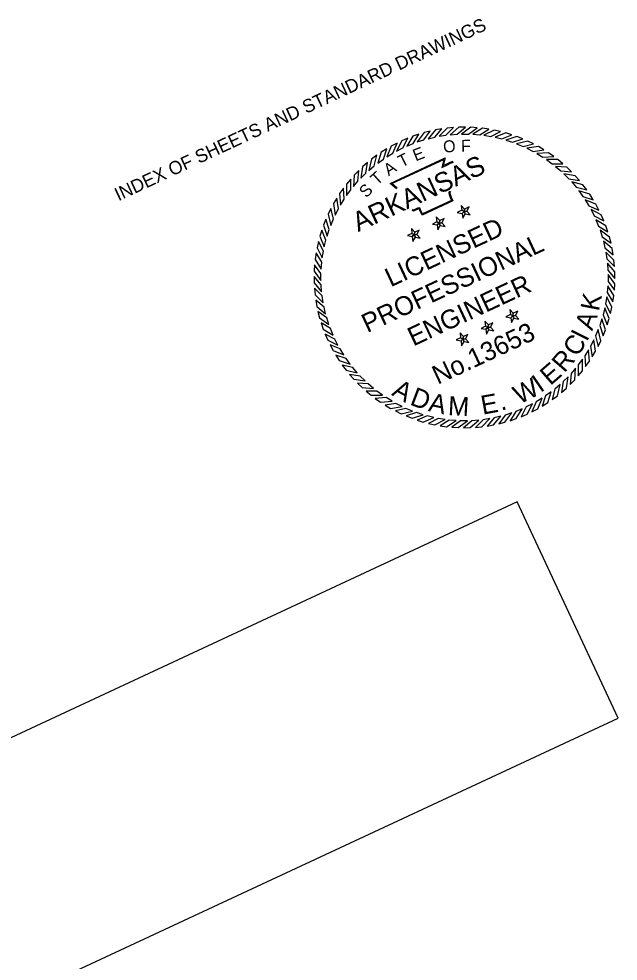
# Model space of a CAD drawing. Extents: x 756658 to 763719, y 1656413 to 1661090.
# Drawn here: x 758763 to 759240, y 1658253 to 1659003 of the extents above; entities that cross this region are included whole.
import ezdxf

# ---------------------------------------------------------------- set-up
doc = ezdxf.new("R2010")
doc.units = 0
doc.layers.add('1', color=7, linetype='Continuous')
doc.layers.add('G-ANNO-STMP-AEW', color=7, linetype='Continuous')

msp = doc.modelspace()

# ---------------------------------------------------------------- linework, layer by layer
at = {"layer": '1'}
msp.add_lwpolyline([(758071.66, 1657901.4), (759239.96, 1658446.19), (759159.72, 1658618.28), (757991.41, 1658073.49)], close=True, dxfattribs=at)
at = {"layer": 'G-ANNO-STMP-AEW'}
for points in [[(759099.83, 1658915.18), (759094.76, 1658914.3), (759088.81, 1658907.32), (759094.22, 1658908.6)], [(759109.17, 1658916.22), (759104.05, 1658915.74), (759097.56, 1658909.26), (759103.05, 1658910.11)], [(759118.56, 1658916.53), (759113.41, 1658916.45), (759106.44, 1658910.5), (759111.98, 1658910.92)], [(759127.94, 1658916.1), (759122.8, 1658916.43), (759115.39, 1658911.04), (759120.94, 1658911.02)], [(759137.26, 1658914.94), (759132.17, 1658915.67), (759124.35, 1658910.88), (759129.89, 1658910.42)], [(759072.72, 1658907.71), (759068, 1658905.67), (759063.83, 1658897.5), (759068.79, 1658900.01)], [(759081.55, 1658910.91), (759076.68, 1658909.25), (759071.89, 1658901.43), (759077.03, 1658903.54)], [(759090.61, 1658913.4), (759085.62, 1658912.13), (759080.23, 1658904.71), (759085.53, 1658906.41)], [(759146.46, 1658913.05), (759141.44, 1658914.17), (759133.27, 1658910.01), (759138.76, 1658909.12)], [(759155.49, 1658910.44), (759150.57, 1658911.96), (759142.1, 1658908.45), (759147.5, 1658907.13)], [(759164.28, 1658907.14), (759159.49, 1658909.03), (759150.77, 1658906.2), (759156.05, 1658904.46)], [(759064.16, 1658903.84), (759059.62, 1658901.43), (759056.11, 1658892.96), (759060.85, 1658895.85)], [(759172.78, 1658903.15), (759168.16, 1658905.42), (759159.25, 1658903.27), (759164.38, 1658901.13)], [(759180.95, 1658898.51), (759176.52, 1658901.13), (759167.47, 1658899.69), (759172.41, 1658897.16)], [(759048.1, 1658894.13), (759043.98, 1658891.04), (759041.84, 1658882.13), (759046.08, 1658885.72)], [(759055.94, 1658899.3), (759051.59, 1658896.54), (759048.76, 1658887.82), (759053.27, 1658891.08)], [(759188.73, 1658893.24), (759184.52, 1658896.2), (759175.38, 1658895.48), (759180.11, 1658892.56)], [(759040.68, 1658888.36), (759036.82, 1658884.96), (759035.39, 1658875.9), (759039.33, 1658879.82)], [(759196.07, 1658887.38), (759192.1, 1658890.66), (759182.93, 1658890.66), (759187.42, 1658887.38)], [(759202.92, 1658880.96), (759199.23, 1658884.54), (759190.09, 1658885.26), (759194.3, 1658881.64)], [(759033.74, 1658882.03), (759030.16, 1658878.34), (759029.44, 1658869.19), (759033.07, 1658873.41)], [(759209.26, 1658874.02), (759205.86, 1658877.88), (759196.8, 1658879.32), (759200.72, 1658875.37)], [(759027.32, 1658875.17), (759024.04, 1658871.21), (759024.04, 1658862.04), (759027.32, 1658866.53)], [(759215.02, 1658866.61), (759211.94, 1658870.72), (759203.02, 1658872.86), (759206.62, 1658868.63)], [(759021.46, 1658867.83), (759018.5, 1658863.62), (759019.22, 1658854.48), (759022.14, 1658859.21)], [(759220.19, 1658858.76), (759217.44, 1658863.11), (759208.72, 1658865.94), (759211.97, 1658861.44)], [(759016.19, 1658860.05), (759013.57, 1658855.63), (759015.01, 1658846.57), (759017.55, 1658851.52)], [(759224.73, 1658850.54), (759222.33, 1658855.09), (759213.85, 1658858.6), (759216.74, 1658853.85)], [(759011.55, 1658851.89), (759009.29, 1658847.27), (759011.43, 1658838.35), (759013.57, 1658843.48)], [(759117.49, 1658849.32), (759115.67, 1658850.34), (759112.06, 1658848.66), (759115.96, 1658847.9)], [(759117.49, 1658849.32), (759117.89, 1658851.37), (759115.18, 1658854.28), (759115.67, 1658850.34)], [(759117.49, 1658849.32), (759115.96, 1658847.9), (759116.45, 1658843.95), (759118.38, 1658847.43)], [(759117.49, 1658849.32), (759119.57, 1658849.58), (759121.49, 1658853.05), (759117.89, 1658851.37)], [(759117.49, 1658849.32), (759118.38, 1658847.43), (759122.28, 1658846.67), (759119.57, 1658849.58)], [(759228.61, 1658841.98), (759226.57, 1658846.71), (759218.4, 1658850.87), (759220.91, 1658845.91)], [(759007.57, 1658843.38), (759005.67, 1658838.6), (759008.5, 1658829.88), (759010.24, 1658835.16)], [(759097.67, 1658840.08), (759095.84, 1658841.09), (759092.24, 1658839.41), (759096.14, 1658838.65)], [(759097.67, 1658840.08), (759098.07, 1658842.13), (759095.36, 1658845.03), (759095.84, 1658841.09)], [(759097.67, 1658840.08), (759096.14, 1658838.65), (759096.62, 1658834.71), (759098.55, 1658838.18)], [(759097.67, 1658840.08), (759099.74, 1658840.33), (759101.67, 1658843.81), (759098.07, 1658842.13)], [(759097.67, 1658840.08), (759098.55, 1658838.18), (759102.45, 1658837.43), (759099.74, 1658840.33)], [(759231.81, 1658833.15), (759230.14, 1658838.02), (759222.32, 1658842.81), (759224.43, 1658837.67)], [(759004.26, 1658834.59), (759002.74, 1658829.67), (759006.25, 1658821.2), (759007.57, 1658826.6)], [(759077.84, 1658830.83), (759078.24, 1658832.88), (759075.53, 1658835.79), (759076.01, 1658831.85)], [(759077.84, 1658830.83), (759079.91, 1658831.09), (759081.84, 1658834.56), (759078.24, 1658832.88)], [(759234.3, 1658824.1), (759233.02, 1658829.08), (759225.6, 1658834.47), (759227.3, 1658829.18)], [(759001.65, 1658825.57), (759000.53, 1658820.55), (759004.69, 1658812.38), (759005.58, 1658817.86)], [(759077.84, 1658830.83), (759076.01, 1658831.85), (759072.41, 1658830.17), (759076.31, 1658829.41)], [(759077.84, 1658830.83), (759076.31, 1658829.41), (759076.8, 1658825.46), (759078.72, 1658828.94)], [(759077.84, 1658830.83), (759078.72, 1658828.94), (759082.62, 1658828.18), (759079.91, 1658831.09)], [(759236.07, 1658814.87), (759235.19, 1658819.94), (759228.22, 1658825.89), (759229.5, 1658820.49)], [(758999.76, 1658816.36), (758999.03, 1658811.27), (759003.83, 1658803.45), (759004.28, 1658808.99)], [(759237.12, 1658805.54), (759236.64, 1658810.66), (759230.15, 1658817.14), (759231, 1658811.65)], [(758998.6, 1658807.04), (758998.27, 1658801.91), (759003.66, 1658794.49), (759003.68, 1658800.05)], [(759237.43, 1658796.15), (759237.35, 1658801.29), (759231.39, 1658808.26), (759231.81, 1658802.72)], [(758998.17, 1658797.66), (758998.25, 1658792.52), (759004.2, 1658785.54), (759003.79, 1658791.09)], [(759237, 1658786.76), (759237.32, 1658791.9), (759231.93, 1658799.32), (759231.92, 1658793.76)], [(758998.48, 1658788.27), (758998.96, 1658783.15), (759005.45, 1658776.67), (759004.59, 1658782.16)], [(759235.84, 1658777.44), (759236.56, 1658782.54), (759231.77, 1658790.35), (759231.32, 1658784.81)], [(759233.94, 1658768.24), (759235.07, 1658773.26), (759230.91, 1658781.43), (759230.02, 1658775.95)], [(758999.53, 1658778.94), (759000.41, 1658773.87), (759007.38, 1658767.91), (759006.1, 1658773.32)], [(759231.34, 1658759.22), (759232.85, 1658764.13), (759229.34, 1658772.61), (759228.03, 1658767.21)], [(759001.3, 1658769.71), (759002.58, 1658764.73), (759009.99, 1658759.34), (759008.29, 1658764.63)], [(759156.21, 1658766.3), (759154.38, 1658767.32), (759150.78, 1658765.64), (759154.68, 1658764.88)], [(759156.21, 1658766.3), (759156.6, 1658768.35), (759153.89, 1658771.26), (759154.38, 1658767.32)], [(759156.21, 1658766.3), (759154.68, 1658764.88), (759155.16, 1658760.93), (759157.09, 1658764.41)], [(759156.21, 1658766.3), (759158.28, 1658766.56), (759160.2, 1658770.03), (759156.6, 1658768.35)], [(759156.21, 1658766.3), (759157.09, 1658764.41), (759160.99, 1658763.65), (759158.28, 1658766.56)], [(759003.79, 1658760.66), (759005.46, 1658755.79), (759013.27, 1658751), (759011.16, 1658756.14)], [(759136.38, 1658757.06), (759134.55, 1658758.07), (759130.95, 1658756.39), (759134.85, 1658755.63)], [(759136.38, 1658757.06), (759136.78, 1658759.11), (759134.07, 1658762.01), (759134.55, 1658758.07)], [(759136.38, 1658757.06), (759138.45, 1658757.31), (759140.38, 1658760.79), (759136.78, 1658759.11)], [(759136.38, 1658757.06), (759137.26, 1658755.16), (759141.16, 1658754.41), (759138.45, 1658757.31)], [(759228.03, 1658750.43), (759229.93, 1658755.21), (759227.09, 1658763.93), (759225.36, 1658758.65)], [(759006.99, 1658751.82), (759009.03, 1658747.1), (759017.2, 1658742.94), (759014.69, 1658747.9)], [(759116.55, 1658747.81), (759116.95, 1658749.86), (759114.24, 1658752.77), (759114.73, 1658748.83)], [(759116.55, 1658747.81), (759118.63, 1658748.07), (759120.55, 1658751.54), (759116.95, 1658749.86)], [(759136.38, 1658757.06), (759134.85, 1658755.63), (759135.34, 1658751.69), (759137.26, 1658755.16)], [(759224.04, 1658741.92), (759226.31, 1658746.54), (759224.17, 1658755.45), (759222.03, 1658750.33)], [(759010.87, 1658743.27), (759013.27, 1658738.72), (759021.74, 1658735.21), (759018.85, 1658739.96)], [(759116.55, 1658747.81), (759114.73, 1658748.83), (759111.13, 1658747.15), (759115.03, 1658746.39)], [(759116.55, 1658747.81), (759115.03, 1658746.39), (759115.51, 1658742.44), (759117.44, 1658745.92)], [(759116.55, 1658747.81), (759117.44, 1658745.92), (759121.34, 1658745.16), (759118.63, 1658748.07)], [(759219.4, 1658733.75), (759222.02, 1658738.18), (759220.59, 1658747.24), (759218.05, 1658742.29)], [(759015.4, 1658735.04), (759018.16, 1658730.7), (759026.88, 1658727.87), (759023.63, 1658732.37)], [(759214.13, 1658725.98), (759217.1, 1658730.18), (759216.38, 1658739.33), (759213.46, 1658734.6)], [(759208.27, 1658718.64), (759211.55, 1658722.6), (759211.55, 1658731.77), (759208.27, 1658727.28)], [(759020.57, 1658727.2), (759023.66, 1658723.09), (759032.58, 1658720.94), (759028.98, 1658725.18)], [(759026.34, 1658719.79), (759029.74, 1658715.93), (759038.8, 1658714.49), (759034.88, 1658718.43)], [(759201.85, 1658711.78), (759205.44, 1658715.47), (759206.15, 1658724.61), (759202.53, 1658720.4)], [(759032.67, 1658712.85), (759036.37, 1658709.27), (759045.51, 1658708.55), (759041.29, 1658712.17)], [(759194.92, 1658705.45), (759198.78, 1658708.85), (759200.21, 1658717.9), (759196.27, 1658713.99)], [(759039.53, 1658706.43), (759043.49, 1658703.15), (759052.66, 1658703.15), (759048.18, 1658706.43)], [(759179.66, 1658694.51), (759184, 1658697.26), (759186.84, 1658705.98), (759182.33, 1658702.73)], [(759187.5, 1658699.68), (759191.62, 1658702.77), (759193.76, 1658711.68), (759189.52, 1658708.09)], [(759046.87, 1658700.57), (759051.08, 1658697.61), (759060.22, 1658698.33), (759055.49, 1658701.25)], [(759171.43, 1658689.97), (759175.98, 1658692.38), (759179.49, 1658700.85), (759174.74, 1658697.96)], [(759054.65, 1658695.3), (759059.08, 1658692.68), (759068.13, 1658694.11), (759063.19, 1658696.65)], [(759062.82, 1658690.66), (759067.43, 1658688.39), (759076.35, 1658690.53), (759071.22, 1658692.68)], [(759154.05, 1658682.9), (759158.91, 1658684.56), (759163.71, 1658692.38), (759158.56, 1658690.27)], [(759162.88, 1658686.09), (759167.6, 1658688.13), (759171.76, 1658696.3), (759166.8, 1658693.8)], [(759071.32, 1658686.67), (759076.1, 1658684.78), (759084.82, 1658687.61), (759079.54, 1658689.34)], [(759080.11, 1658683.37), (759085.03, 1658681.85), (759093.5, 1658685.36), (759088.1, 1658686.67)], [(759089.14, 1658680.76), (759094.16, 1658679.63), (759102.33, 1658683.8), (759096.84, 1658684.68)], [(759098.34, 1658678.87), (759103.43, 1658678.14), (759111.25, 1658682.93), (759105.71, 1658683.38)], [(759107.66, 1658677.7), (759112.79, 1658677.38), (759120.21, 1658682.77), (759114.65, 1658682.79)], [(759117.04, 1658677.28), (759122.19, 1658677.35), (759129.16, 1658683.31), (759123.62, 1658682.89)], [(759126.43, 1658677.59), (759131.55, 1658678.07), (759138.04, 1658684.55), (759132.54, 1658683.7)], [(759135.77, 1658678.63), (759140.83, 1658679.51), (759146.79, 1658686.49), (759141.38, 1658685.21)], [(759144.99, 1658680.41), (759149.97, 1658681.68), (759155.36, 1658689.1), (759150.07, 1658687.4)]]:
    msp.add_lwpolyline(points, close=True, dxfattribs=at)
for points in [[(759063.73, 1658867.5), (759058.66, 1658871.79), (759102.38, 1658892.21), (759100.86, 1658885.91), (759103.81, 1658887.34), (759106.28, 1658888.53), (759108.89, 1658889.41)], [(759064.23, 1658868.08), (759060.06, 1658871.6), (759101.26, 1658890.84), (759099.74, 1658884.53), (759104.15, 1658886.65), (759106.57, 1658887.82), (759109.13, 1658888.69)], [(759106.59, 1658865.17), (759106.13, 1658864.21), (759106.31, 1658863.19), (759107.12, 1658860.81), (759108.53, 1658857.79), (759084.11, 1658846.4), (759082.21, 1658850.48), (759081.79, 1658851.39), (759080.66, 1658851.23), (759077.18, 1658849.61), (759076.13, 1658850.27)], [(759105.91, 1658865.5), (759105.34, 1658864.33), (759105.56, 1658863), (759106.41, 1658860.52), (759107.51, 1658858.16), (759084.48, 1658847.42), (759082.9, 1658850.81), (759082.24, 1658852.23), (759080.44, 1658851.97), (759077.23, 1658850.48), (759076.53, 1658850.92)]]:
    msp.add_lwpolyline(points, dxfattribs=at)

# ---------------------------------------------------------------- texts
at = {"layer": '1'}
msp.add_text('INDEX OF SHEETS AND STANDARD DRAWINGS', height=10.5516, rotation=25, dxfattribs=at).set_placement((758842.67, 1658857.42))
at = {"layer": 'G-ANNO-STMP-AEW'}
for s, height, rotation, p in [('E', 9.52, 21.67203, (759078.99, 1658889.2)), ('O', 9.52, 6.2218, (759101.32, 1658896.01)), ('F', 9.52, 0.36282, (759115.07, 1658896.88)), ('ARKANSAS', 15.535, 25, (759033.27, 1658832.89)), ('T', 9.52, 26.47887, (759067.83, 1658884.31)), ('A', 9.52, 33.67877, (759057.49, 1658877.4)), ('T', 9.52, 41.90148, (759048.29, 1658869.78)), ('S', 9.52, 44.77256, (759039.62, 1658859.74)), ('LICENSED', 15.039, 25, (759059.07, 1658788.97)), ('PROFESSIONAL', 15.0392, 25, (759040.49, 1658752.56)), ('ENGINEER', 15.039, 25, (759077.09, 1658741.87)), ('K', 15.04, 78.84706, (759224.58, 1658769.47)), ('A', 15.04, 70.18496, (759219.35, 1658754.01)), ('No.13653', 14.98, 25, (759096.54, 1658711.39)), ('C', 15.04, 57.13964, (759207.58, 1658733.03)), ('I', 15.04, 63.40573, (759215.05, 1658745.27)), ('R', 15.04, 49.16163, (759197.2, 1658720.44)), ('E', 15.04, 41.01252, (759186.06, 1658710.39)), ('A', 15.04, 330.982, (759059.22, 1658703.52)), ('W', 15.04, 27.1127, (759161.51, 1658695.62)), ('I', 15.04, 34.57533, (759178.1, 1658704.78)), ('D', 15.04, 339.30216, (759073.66, 1658695.91)), ('A', 15.04, 347.62232, (759088.41, 1658690.66)), ('M', 15.04, 356.79687, (759104.41, 1658687.41)), ('E', 15.04, 10.2782, (759132.25, 1658687.66)), ('.', 15.04, 15.85832, (759146.93, 1658690.75))]:
    msp.add_text(s, height=height, rotation=rotation, dxfattribs=at).set_placement(p)

doc.saveas('drawing.dxf')
